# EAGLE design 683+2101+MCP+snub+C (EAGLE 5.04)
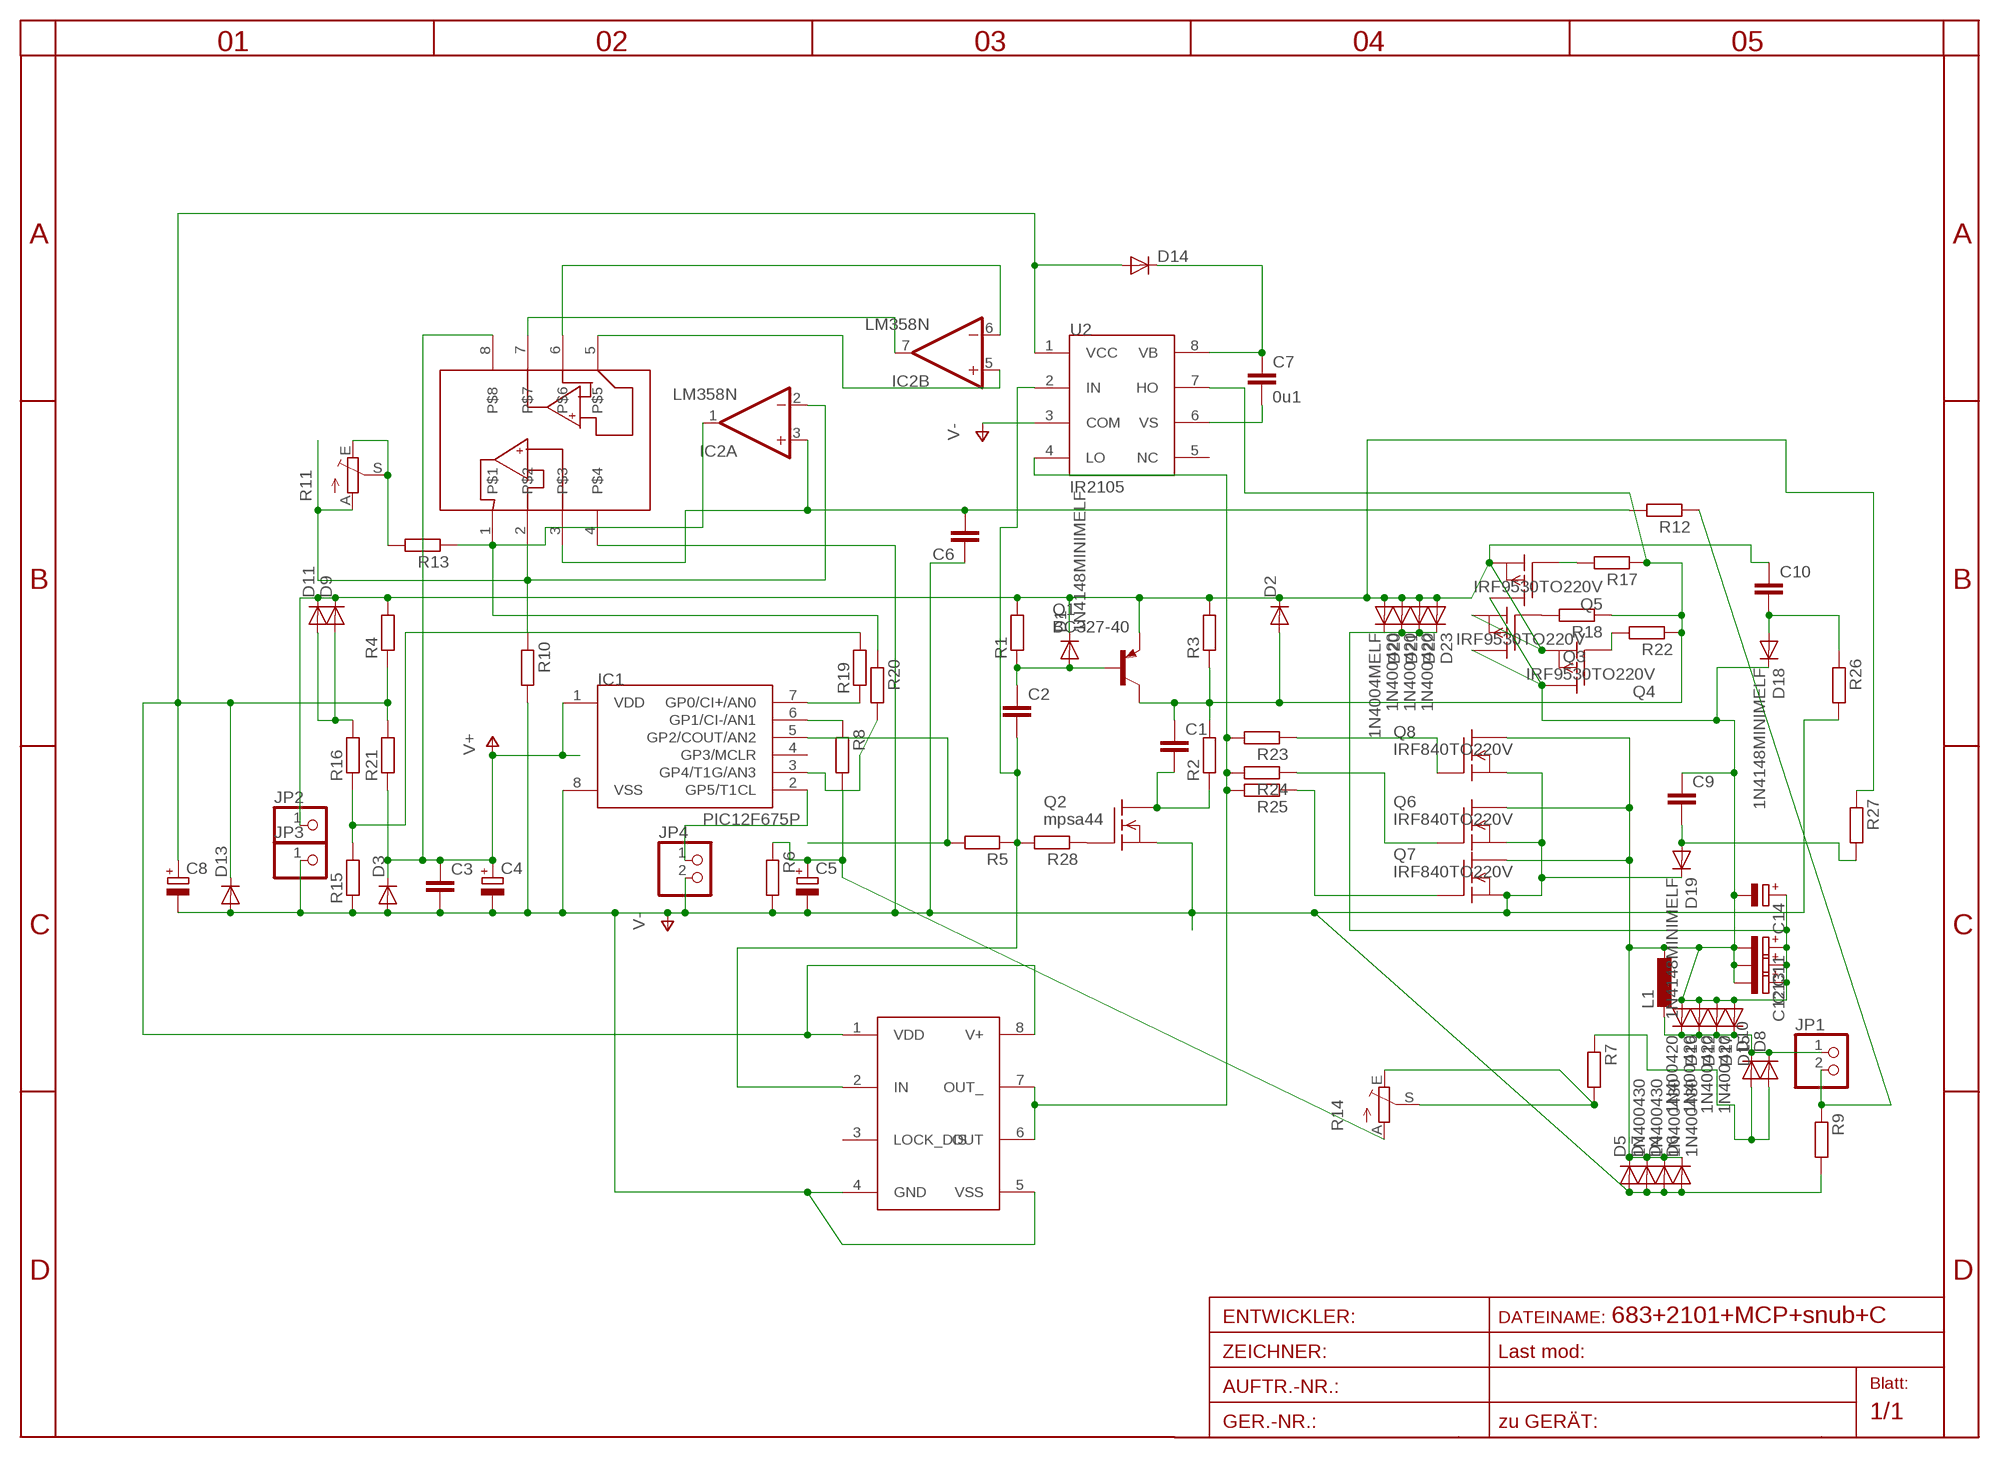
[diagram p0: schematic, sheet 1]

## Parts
C1  C-EU225-074X268  [C225-074X268]
C2  C-EU225-062X268  [C225-062X268]
C3  C-EU050-025X075  [C050-025X075]
C4  CPOL-EU5-13  [2,5-5-FLAT]
C5  CPOL-EU5-13  [2,5-5-FLAT]
C6  C-EU025_050-025X075  [C025_050-025X075]
C7  0u1  C-EU050-030X075  [C050-030X075]
C8  CPOL-EU5-13  [2,5-5-FLAT]
C9  C-EUC1812  [C1812]
C10  C-EUC1812K  [C1812K]
C11  CPOL-EUD  [PANASONIC_D]
C12  CPOL-EUE  [PANASONIC_E]
C13  CPOL-EUE  [PANASONIC_E]
C14  CPOL-EUE  [PANASONIC_E]
D1  1N4148MINIMELF  [MINIMELF]
D2  DIODE-D-5  [D-5]
D3  DIODE-D-2.5  [D-2.5]
D4  1N400430  [DO41-30]
D5  1N400430  [DO41-30]
D6  1N400430  [DO41-30]
D7  1N400430  [DO41-30]
D8  DIODE-D-2.5  [D-2.5]
D9  DIODE-D-2.5  [D-2.5]
D10  DIODE-DO41-30  [DO41-30]
D11  DIODE-D-10  [D-10]
D12  1N400420  [DO41-20]
D13  DIODE-D-2.5  [D-2.5]
D14  DIODE-D-5  [D-5]
D15  1N400420  [DO41-20]
D16  1N400420  [DO41-20]
D17  1N400420  [DO41-20]
D18  1N4148MINIMELF  [MINIMELF]
D19  1N4148MINIMELF  [MINIMELF]
D20  1N4004MELF  [MELF-MLL41]
D21  1N400420  [DO41-20]
D22  1N400420  [DO41-20]
D23  1N400420  [DO41-20]
IC1  PIC12F675P  [DIL8]
IC2  LM358N  [DIL08]
IC3  TC4432X  [SO-08]
JP1  PINHD-1X2  [1X02]
JP2  PINHD-1X1  [1X01]
JP3  PINHD-1X1  [1X01]
JP4  PINHD-1X2  [1X02]
L1  L-EU0204/7  [0204/7]
Q1  BC327-40  [TO92-EBC]
Q2  mpsa44  TN0604N3  [TO-92]
Q3  IRF9530TO220V  [TO220V]
Q4  IRF9530TO220V  [TO220V]
Q5  IRF9530TO220V  [TO220V]
Q6  IRF840TO220V  [TO220V]
Q7  IRF840TO220V  [TO220V]
Q8  IRF840TO220V  [TO220V]
R1  R-EU_0204/2V  [0204V]
R2  R-EU_0207/25  [0207/25]
R3  R-EU_0204/2V  [0204V]
R4  R-EU_0207/10  [0207/10]
R5  R-EU_0207/40  [0207/40]
R6  R-EU_0204/5  [0204/5]
R7  R-EU_0207/15  [0207/15]
R8  R-EU_0207/10  [0207/10]
R9  R-EU_0309/10  [0309/10]
R10  R-EU_0207/15  [0207/15]
R11  TRIM_EU-CIP20C-4MM  [CIP20C-4MM]
R12  R-EU_0207/30  [0207/30]
R13  R-EU_0207/40  [0207/40]
R14  TRIM_EU-CIP20C-4MM  [CIP20C-4MM]
R15  R-EU_0204/5  [0204/5]
R16  R-EU_0207/25  [0207/25]
R17  R-EU_R1206  [R1206]
R18  R-EU_R1206  [R1206]
R19  R-EU_0204/5  [0204/5]
R20  R-EU_0204/5  [0204/5]
R21  R-EU_0207/10  [0207/10]
R22  R-EU_R1206  [R1206]
R23  R-EU_R1206  [R1206]
R24  R-EU_R1206  [R1206]
R25  R-EU_R1206  [R1206]
R26  R-EU_0207/25  [0207/25]
R27  R-EU_0207/30  [0207/30]
R28  R-EU_R0805  [R0805]
U2  IR2105  [DIL08]
U$1  MCP6042SOIC  [SO-08]

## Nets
BB: C2.2 IC3.2(IN) R5.1 R28.2 U2.2(IN)
DRAIN: C9.1 C11.+ C11.- C12.+ C12.- C13.+ C13.- C14.+ C14.- D4.C D5.C D6.C D7.C D12.A D15.A D16.A D17.A D18.C D20.C D21.C D22.C D23.C L1.1 Q3.2(D) Q4.2(D) Q5.2(D) Q6.2(D) Q7.2(D) Q8.2(D)
GATE: C1.1 D2.A Q1.C R2.2 R3.1 R17.1 R18.1 R22.1 U2.7(HO)
MPOINT: C5.+ R6.1 R8.2 R14.A
N$1: C1.2 Q2.3(D) R2.1
N$2: IC2.6(B:-IN) U$1.6
N$3: IC1.5(GP2/COUT/AN2) R5.2
N$4: Q3.1(G) R18.2
N$5: IC1.6(GP1/CI-/AN1) R8.1
N$6: IC2.2(A:-IN) R10.1 R11.A U$1.2
N$7: IC2.1(A:OUT) R13.1 R20.1 U$1.1
N$8: Q2.2(G) R28.1
N$9: C6.2 IC2.3(A:+IN) R12.2 U$1.3
N$10: R7.2 R14.E R14.S
N$11: Q5.1(G) R17.2
N$12: R15.2 R16.1 R19.2
N$13: D9.A D11.A R16.2
N$14: IC1.7(GP0/CI+/AN0) R19.1
N$15: IC1.2(GP5/T1CL) JP4.1
N$16: D8.A D10.A R7.1
N$17: IC1.3(GP4/T1G/AN3) R20.2
N$18: IC2.5(B:+IN) U$1.5
N$20: IC2.7(B:OUT) U$1.7
N$21: C7.2 U2.6(VS)
N$23: Q4.1(G) R22.2
N$24: C10.2 D18.A R26.1
N$25: Q7.1(G) R25.1
N$26: Q6.1(G) R24.1
N$27: Q8.1(G) R23.1
N$28: C9.2 D19.A R27.2
N$29: R11.E R11.S R13.2
N$33: IC3.6(OUT) IC3.7(OUT_) R23.2 R24.2 R25.2 U2.4(LO)
OUT+: D8.C D10.C D12.C D15.C D16.C D17.C JP1.1 L1.2
OUT-: JP1.2 R9.1 R12.1
TB: C2.1 D1.A Q1.B R1.1
V+: C3.1 C4.+ D3.C IC1.1(VDD) R21.1 U$1.8
V-: C3.2 C4.- C5.- C6.1 C8.- D3.A D4.A D5.A D6.A D7.A D13.A D19.C IC1.8(VSS) IC3.4(GND) IC3.5(VSS) JP3.1 JP4.2 Q2.1(S) Q6.3(S) Q7.3(S) Q8.3(S) R6.2 R9.2 R10.2 R15.1 R26.2 U2.3(COM) U$1.4
VB: C7.1 D14.C U2.8(VB)
VCC: C8.+ D13.C D14.A IC3.1(VDD) IC3.8(V+) R4.1 R21.2 U2.1(VCC)
VIN: C10.1 D1.C D2.C D9.C D11.C D20.A D21.A D22.A D23.A JP2.1 Q1.E Q3.3(S) Q4.3(S) Q5.3(S) R1.2 R3.2 R4.2 R27.1
Unconnected: IC1.4(GP3/MCLR) IC3.3(LOCK_DIS) U2.5(NC)

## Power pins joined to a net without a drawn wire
V+: IC2.8(P:V+)
V-: IC2.4(P:V-)

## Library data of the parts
C1-C3 C6 C7 C9 C10 = rcl-2:C-EU: CAPACITOR, European symbol
C4 C5 C8 C11-C14 = rcl-2:CPOL-EU: POLARIZED CAPACITOR, European symbol
D1 D18 D19 = diode-1:1N4148: DIODE
D2 D3 D8-D11 D13 D14 = diode-1:DIODE-: DIODE
D4-D7 D12 D15-D17 D20-D23 = diode-1:1N4004: DIODE
IC1 = microchip-5:PIC12F6*: uPC nW 1k Program Flash memory 2x Timer Comparator 10b A/D converter/ 4xIN
IC2 = linear:LM358: OP AMP also LM158; LM258; LM2904 Source: http://cache.national.com/ds/LM/LM158.pdf
IC3 = microchip:TC4432
JP1 JP4 = pinhead:PINHD-1X2: PIN HEADER
JP2 JP3 = pinhead:PINHD-1X1: PIN HEADER
L1 = rcl-2:L-EU: INDUCTOR, European symbol
Q1 = transistor-pnp:BC327*: PNP Transistror
Q2 = transistor-fet:TN0604N3: N-Channel Enhancement MOSFET 40V; 4A; 0,75Ohm
Q3-Q5 = transistor-fet:IRF9530: P-Channel Enhancement MOSFET (HEXFET); -100V; -12A; 0,3Ohm
Q6-Q8 = transistor-fet:IRF840: N-Channel Enhancement MOSFET (HEXFET); 500V; 8A; 0,85Ohm
R1-R10 R12 R13 R15-R28 = rcl-2:R-EU_: RESISTOR, European symbol
R11 R14 = pot:TRIM_EU-: POTENTIOMETER
U2 = irf-2:IR2105: Half bridge driver
U$1 = microchip-3:MCP6042

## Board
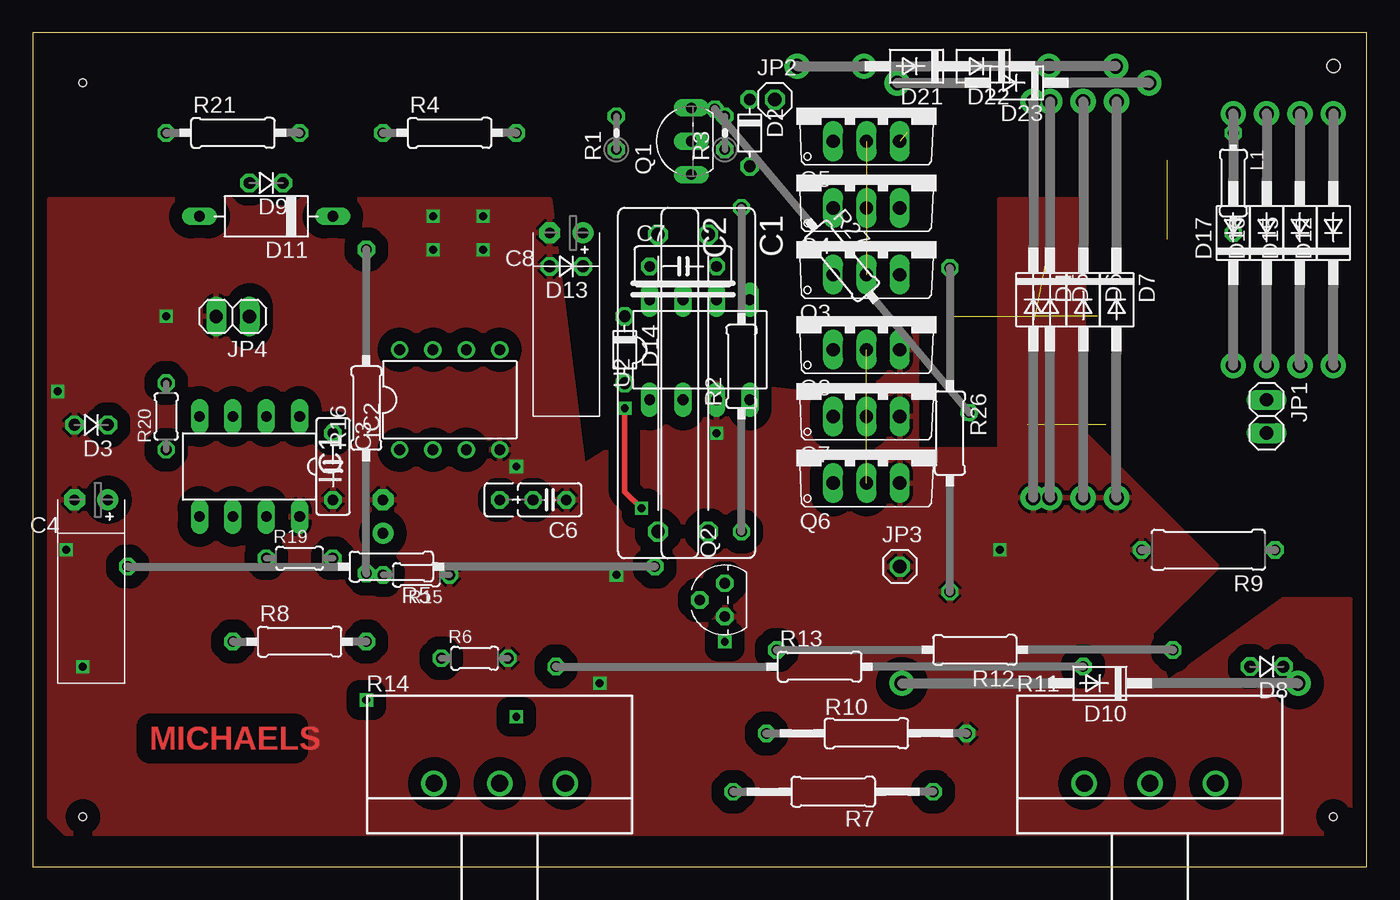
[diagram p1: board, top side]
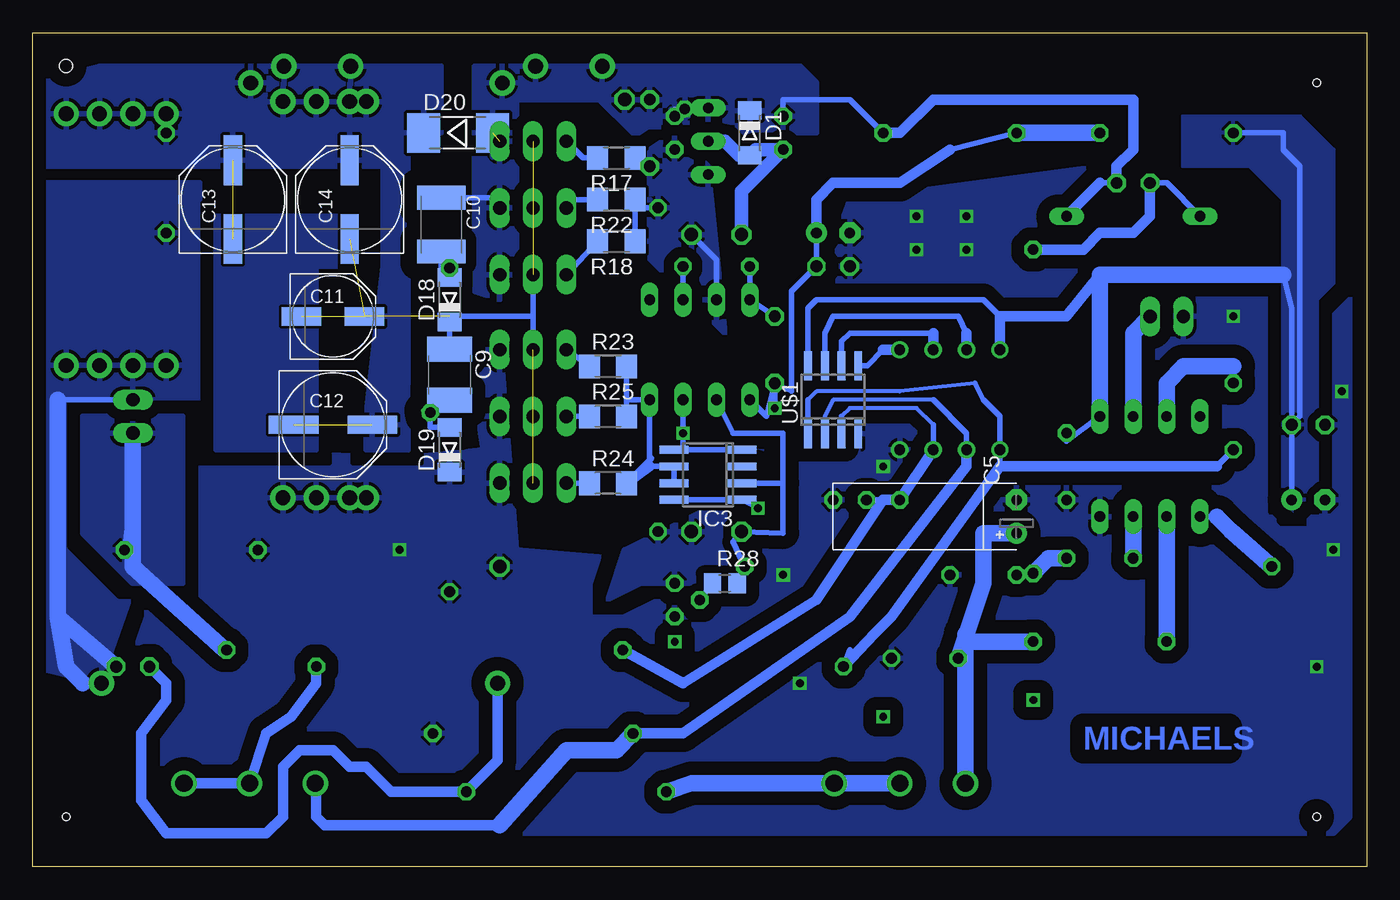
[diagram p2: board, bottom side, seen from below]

Size 101.6 x 63.5 mm. Coordinates in mm from the lower left corner, seen from the top.
Outline: 0,0 101.6,0 101.6,63.5 0,63.5 0,0
Copper layers (1*16): Top 0.035mm / dielectric 1.5mm / Bottom 0.035mm
Design rules "default": minimum track width 10mil, minimum drill 24mil, track to track 8mil, track to pad 8mil, pad to pad 8mil, via to via 8mil, smd to smd 8mil, copper to edge 40mil, drill to drill 8mil, minimum pad ring 10mil, minimum via ring 8mil, stop-mask expansion 4mil, vias tented up to drill 0mil, thermal gap 10mil
Holes 0.6 mm at 3.81,59.69 3.81,3.81 99.06,3.81
Holes 1 mm at 99.06,60.96

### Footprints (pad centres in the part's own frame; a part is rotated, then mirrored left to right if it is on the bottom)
C225-074X268 = drill 1.016 octagon: 1 -11.303,0; 2 11.303,0
C225-062X268 = drill 1.016 octagon: 1 -11.303,0; 2 11.303,0
C050-025X075 = drill 0.813 octagon: 1 -2.54,0; 2 2.54,0
2,5-5-FLAT = drill 0.813 pad 1.6 round: + -1.27,0 | drill 0.813 pad 1.6 octagon: - 1.27,0
C025_050-025X075 = drill 0.813 octagon: 1 -1.27,0; 2 1.27,0; 3 3.81,0
C050-030X075 = drill 0.813 octagon: 1 -2.54,0; 2 2.54,0
C1812 = smd 1.9 x 3.4: 1 -1.95,0; 2 1.95,0
C1812K = smd 1.8 x 3.7: 1 -2.05,0; 2 2.05,0
PANASONIC_D = smd 3 x 1.4: + 2.4,0; - -2.4,0
PANASONIC_E = smd 3.8 x 1.4: + 3,0; - -3,0
MINIMELF = smd 1.4 x 1.8: A 1.7,0; C -1.7,0
D-5 = drill 0.9 octagon: A 2.54,0; C -2.54,0
D-2.5 = drill 0.9 octagon: A 1.27,0; C -1.27,0
DO41-30 = drill 1.118 pad 1.93 round: A 15.08,0; C -15.08,0
D-10 = drill 0.813 long: A 5.08,0; C -5.08,0
DO41-20 = drill 1.118 pad 1.93 round: A 9.08,0; C -10.08,0
MELF-MLL41 = smd 2.5 x 3: A 2.625,0; C -2.625,0
DIL8 = drill 0.813 long: 1 -3.81,-3.81; 2 -1.27,-3.81; 3 1.27,-3.81; 4 3.81,-3.81; 5 3.81,3.81; 6 1.27,3.81; 7 -1.27,3.81; 8 -3.81,3.81
DIL08 = drill 0.813 pad 1.27 round: 1 -3.81,-3.81; 2 -1.27,-3.81; 3 1.27,-3.81; 4 3.81,-3.81; 5 3.81,3.81; 6 1.27,3.81; 7 -1.27,3.81; 8 -3.81,3.81
SO-08 = smd 0.6 x 2.2: 1 -1.905,-2.6; 2 -0.635,-2.6; 3 0.635,-2.6; 4 1.905,-2.6; 5 1.905,2.6; 6 0.635,2.6; 7 -0.635,2.6; 8 -1.905,2.6
1X02 = drill 1.016 long: 1 -1.27,0; 2 1.27,0
1X01 = drill 1.016 octagon: 1 0,0
0204/7 = drill 0.813 octagon: 1 -3.81,0; 2 3.81,0
TO92-EBC = drill 0.813 long: B 0,-1.27; C -2.54,-1.27; E 2.54,-1.27
TO-92 = drill 0.813 octagon: 1 -1.27,0; 2 0,1.905; 3 1.27,0
TO220V = drill 1.016 long: 1 -2.54,-2.54; 2 0,-2.54; 3 2.54,-2.54
0204V = drill 0.813 octagon: 1 -1.27,0; 2 1.27,0
0207/25 = drill 0.813 octagon: 1 -12.58,0; 2 12.08,0
0207/10 = drill 0.813 octagon: 1 -5.08,0; 2 5.08,0
0207/40 = drill 0.813 octagon: 1 -20.08,0; 2 20.08,0
0204/5 = drill 0.813 octagon: 1 -2.54,0; 2 2.54,0
0207/15 = drill 0.813 octagon: 1 -7.62,0; 2 7.62,0
0309/10 = drill 0.813 octagon: 1 -5.08,0; 2 5.08,0
CIP20C-4MM = drill 1.3 pad 1.93 round: A -5,0; E 5,0; S 0,0
0207/30 = drill 0.813 octagon: 1 -15.08,0; 2 15.08,0
R1206 = smd 1.6 x 1.803: 1 -1.422,0; 2 1.422,0
R0805 = smd 1.3 x 1.5: 1 -0.95,0; 2 0.95,0
DIL08' = drill 0.813 long: 1 -3.81,-3.81; 2 -1.27,-3.81; 3 1.27,-3.81; 4 3.81,-3.81; 5 3.81,3.81; 6 1.27,3.81; 7 -1.27,3.81; 8 -3.81,3.81

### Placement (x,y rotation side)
C1  51.44,36.83 270 top
C2  47.62,36.83 270 top
C3  22.86,30.48 270 top
C4  4.45,27.94 180 top
C5  26.67,26.67 90 bottom
C6  39.37,27.94 180 top
C7  49.53,45.72 0 top
C8  40.64,48.26 180 top
C9  69.85,37.47 270 bottom
C10  70.48,48.9 270 bottom
C11  78.74,41.91 0 bottom
C12  78.74,33.66 0 bottom
C13  86.36,50.8 90 bottom
C14  77.47,50.8 90 bottom
D1  46.99,55.88 270 bottom
D2  54.61,55.88 270 top
D3  4.45,33.66 180 top
D4  76.2,43.18 270 top
D5  77.47,43.18 270 top
D6  80.01,43.18 270 top
D7  82.55,43.18 270 top
D8  93.98,15.24 180 top
D9  17.78,52.07 180 top
D10  81.28,13.97 180 top
D11  17.78,49.53 180 top
D12  99.06,48.26 90 top
D13  40.64,45.72 180 top
D14  45.09,39.37 270 top
D15  96.52,48.26 90 top
D16  93.98,48.26 90 top
D17  91.44,48.26 90 top
D18  69.85,43.18 90 bottom
D19  69.85,31.75 90 bottom
D20  69.22,55.88 0 bottom
D21  67.31,60.96 180 top
D22  72.39,60.96 180 top
D23  74.93,59.69 180 top
IC1  16.51,30.48 180 top
IC2  31.75,35.56 0 top
IC3  50.16,29.84 90 bottom
JP1  93.98,34.29 270 top
JP2  56.52,58.42 0 top
JP3  66.04,22.86 0 top
JP4  15.24,41.91 180 top
L1  91.44,52.07 270 top
Q1  48.9,55.24 90 top
Q2  52.7,20.32 90 top
Q3  63.5,47.62 0 top
Q4  63.5,52.7 0 top
Q5  63.5,57.78 0 top
Q6  63.5,31.75 0 top
Q7  63.5,36.83 0 top
Q8  63.5,41.91 0 top
R1  44.45,55.88 90 top
R2  53.98,38.1 90 top
R3  52.7,55.88 90 top
R4  31.75,55.88 0 top
R5  27.3,22.86 180 top
R6  33.66,15.88 0 top
R7  60.96,5.71 180 top
R8  20.32,17.14 0 top
R9  89.53,24.13 180 top
R10  63.5,10.16 0 top
R11  85.09,6.35 0 top
R12  71.75,16.51 180 top
R13  59.93,15.24 0 top
R14  35.56,6.35 0 top
R15  29.21,22.23 180 top
R16  25.4,34.92 90 top
R17  57.15,53.98 180 bottom
R18  57.15,47.62 180 bottom
R19  20.32,23.5 0 top
R20  10.16,34.29 90 top
R21  15.24,55.88 0 top
R22  57.15,50.8 180 bottom
R23  57.78,38.1 0 bottom
R24  57.78,29.21 0 bottom
R25  57.78,34.29 0 bottom
R26  69.85,33.02 270 top
R27  61.63,46.14 310 top
R28  48.9,21.59 0 bottom
U2  IR2105  [DIL08']  50.8,39.37 0 top
U$1  40.64,35.56 0 bottom

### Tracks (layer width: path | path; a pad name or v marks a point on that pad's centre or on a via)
BB
  Bottom 0.406: 44.45,29.21 44.45,25.4 C2.2 48.26,24.77 R5.1 R28.2 | 44.45,29.21 IC3.2 | 44.45,29.21 44.45,33.02 48.26,33.02 U2.2
DRAIN  (9 unrouted)
  Bottom 0.406: C9.1 D18.C 69.85,41.91 63.5,41.91 | Q8.2 63.5,41.91 | 63.5,41.91 Q3.2
  pour Bottom (isolate 1.016, rank 5): 101.6,53.34 74.93,53.34 70.48,55.88 70.48,60.96 96.52,60.96 101.6,59.69
  pour Bottom (isolate 1.27): 76.2,34.29 76.2,31.75 73.03,31.75 73.03,55.88 77.47,55.88 74.93,53.34 74.93,45.72
GATE
  Bottom 0.406: C1.1 49.53,46.23 U2.7 | R18.1 R22.1 55.11,50.18 R2.2 | D2.A 55.09,53.34 R17.1
  pour Bottom (isolate 0.813, rank 2): 50.16,53.34 52.7,55.88 54.61,54.61 54.61,46.35 48.9,40.64
MPOINT
  Bottom 0.406: 29.84,17.14 R6.1 30.56,17.7
  Bottom 1.27: 29.84,17.14 R8.2 | R14.A 30.56,17.7 | R6.1 29.21,21.59 29.21,25.4 C5.+
N$1
  pour Bottom (isolate 0.61, rank 3): 48.9,27.94 56.52,24.13 57.78,20.32 55.24,21.59 48.9,21.59
N$2
  Bottom 0.406: U$1.6 40.01,40.01 39.37,40.64 33.02,40.64
  Bottom 0.813: IC2.6 33.02,40.64
N$3
  Bottom 0.406: 11.43,26.67 IC1.5
  Bottom 1.27: R5.2 10.4,25.64 11.43,26.67
N$4
  Bottom 0.406: R18.2 Q3.1
N$5
  Bottom 1.27: R8.1 IC1.6
N$6
  Bottom 0.305: U$1.2 41.27,34.29 40.64,35.56 33.02,35.56
  Bottom 0.406: 33.02,35.56 30.48,33.02 IC2.2
  Bottom 0.813: R10.1 52.07,10.16 39.37,19.05 30.48,30.48 IC2.2 | 66.04,3.17 79.38,3.17 80.01,3.81 80.01,6.27 R11.A
  Bottom 1.27: 66.04,3.17 60.96,8.89 57.15,8.89 R10.1
N$7
  Bottom 0.305: 29.84,36.83 35.56,36.2 41.91,36.2 42.55,35.56
  Bottom 0.406: 29.84,36.83 29.21,35.56 27.94,34.29 IC2.1 27.94,30.48 | 42.55,35.56 U$1.1 | R13.1 39.37,16.51 | R20.1 11.43,30.48
  Bottom 0.813: 11.43,30.48 27.94,30.48 36.2,19.05 37.47,17.78 R13.1
N$8
  Bottom 0.406: R28.1 Q2.2
N$9
  Bottom 0.305: 33.02,33.66 34.29,34.92 39.37,34.92 40.01,34.29
  Bottom 0.406: IC2.3 33.02,33.66 | 40.01,34.29 U$1.3 | 36.83,27.94 C6.2
  Bottom 0.813: IC2.3 35.56,27.94 36.83,27.94 41.91,20.32 52.07,13.97 R12.2
N$10
  Bottom 1.27: R14.S R14.E 51.44,6.35 R7.2
N$11
  Bottom 0.406: R17.2 59.69,53.98 Q5.1
N$12
  Bottom 0.406: R15.2 25.52,22.23 R16.1
  Bottom 1.27: R19.2 24.25,23.5 R16.1
N$13
  Bottom 0.406: D9.A 15.24,52.07 D11.A | 25.39,46.99 R16.2
  Bottom 0.813: D9.A 16.51,49.53 17.78,48.26 20.32,48.26 21.59,46.99 25.39,46.99
N$14
  Bottom 1.27: R19.1 IC1.7
N$15
  Bottom 1.27: IC1.2 17.78,40.64 JP4.1
N$16
  Bottom 0.813: D8.A 91.44,13.97 91.44,12.7 93.34,10.16 93.34,5.08 91.44,2.54 83.82,2.54 82.55,3.81 82.55,7.62 81.28,8.89 78.74,8.89 77.47,7.62 76.2,7.62 74.3,5.71 R7.1 66.2,8.1 D10.A
N$17
  Bottom 0.406: R20.2 10.16,38.1
  Bottom 1.27: 10.16,38.1 13.97,38.1 15.24,36.83 IC1.3
N$18
  Bottom 0.406: U$1.5 38.04,38.16 36.83,39.37
  Bottom 0.813: IC2.5 36.83,39.37
N$20
  Bottom 0.406: U$1.7 41.27,40.64 40.64,41.91 31.11,41.91 30.48,40.64
  Bottom 0.813: IC2.7 30.48,40.64
N$21
  Bottom 0.406: U2.6 C7.2
N$22  (via drill 0.6)
  other vias: 36.83,11.43
N$23
  Bottom 0.406: R22.2 60.33,50.8 Q4.1
N$24
  Bottom 0.406: D18.A R26.1 70.48,45.6 C10.2
N$25
  Bottom 0.406: R25.1 Q7.1
N$26
  Bottom 0.406: R24.1 Q6.1
N$27
  Bottom 0.406: R23.1 Q8.1
N$28
  Bottom 0.406: C9.2 71.33,35.52 R27.2 71.33,33.45 D19.A
N$29
  Bottom 0.813: R13.2 80.01,13.97 81.92,11.43 83.82,10.16 R11.S R11.E
N$30  (via drill 0.6)
  other vias: 25.4,12.7
N$31
  pour Bottom: 77.47,49.53 87.63,49.53 87.63,31.75 80.01,31.75 80.01,45.72 77.47,45.72
N$33
  Bottom 0.406: 54.61,30.96 U2.4 56.36,35.56 | R24.2 54.61,30.96 | 56.36,35.56 R25.2 | 56.36,35.56 R23.2 | IC3.7 IC3.6 54.61,30.48 | 54.61,30.96 54.46,31.11
  Bottom 0.813: 54.61,30.48 R24.2
N$35  (via drill 0.6)
  other vias: 52.7,17.14
OUT+
  Bottom 0.406: 99.69,35.56 JP1.1 | D10.C 97.79,13.97
  Bottom 1.27: 99.69,19.05 99.69,35.56 | 99.69,19.05 D8.C | 99.69,19.05 99.06,15.24 97.79,13.97
  pour Bottom (isolate 1.016, rank 5): 88.9,52.07 101.6,52.07 101.6,15.24 96.52,13.97 88.9,35.56
OUT-
  Bottom 0.406: R12.1 87,16.51 | 93.98,29.21 R9.1
  Bottom 1.27: 87,16.51 93.98,22.86 93.98,29.21 JP1.2
  pour Bottom (isolate 0.813): 90.17,34.29 97.79,34.29 97.79,33.02 97.79,25.4 93.98,21.59 90.17,21.59 90.17,31.75
TB
  Bottom 1.016: C2.1 47.62,51.44 R1.1 46.56,54.61 D1.A 47.83,54.18 48.9,55.24 Q1.B
V+
  Bottom 0.406: R21.1 6.35,55.88 6.35,54.61 5.08,53.34 5.08,34.29 D3.C | D3.C 5.71,42.55 6.35,45.09 | IC1.1 22.86,32.38 C3.1 | U$1.8 42.55,42.55 41.91,43.18 29.21,43.18 27.94,41.91 | C4.+ D3.C
  Bottom 0.813: 20.32,45.09 22.86,41.91 27.94,41.91 IC2.8
  Bottom 1.27: 6.35,45.09 20.32,45.09 IC1.1
  pour Bottom (isolate 0.61, rank 3): 13.97,57.15 5.08,57.15 2.54,54.61 2.54,44.45 3.81,43.18 3.81,27.94 5.08,26.67 6.35,27.94 6.35,50.8 8.89,53.34 13.97,53.34
V-  (via drill 0.6)
  Bottom 0.406: IC3.4 52.07,31.75 | 52.07,31.75 IC3.5 | 52.07,31.75 v52.07,33.02 U2.3
  other vias: 36.83,30.48 44.45,22.23 43.18,13.97 73.66,24.13 10.16,41.91 30.48,49.53 34.29,49.53 34.29,46.99 30.48,46.99 1.91,36.2 2.54,24.13 3.81,15.24
  pour Top (isolate 1.016, rank 5): 1.27,50.8 39.37,50.8 41.91,30.48 52.07,36.83 63.5,35.56 64.77,40.64 67.31,40.64 67.31,31.75 73.66,31.75 73.66,50.8 80.01,50.8 80.01,33.02 90.17,22.86 85.09,17.78 86.36,13.97 95.25,20.32 100.33,20.32 100.33,3.81 99.06,2.54 2.54,2.54 1.27,3.81
  pour Bottom (isolate 1.016, rank 6): 1.27,55.88 39.37,50.8 49.53,22.86 64.77,24.13 66.04,40.64 68.58,40.64 67.31,31.75 73.66,31.11 86.36,31.75 88.9,31.75 92.71,27.94 93.98,25.4 93.98,22.86 97.79,22.86 100.33,20.32 100.33,3.81 99.06,2.54 2.54,2.54 1.27,3.81
VB
  Bottom 0.406: C7.1 U2.8 D14.C
VCC  (via drill 0.6)
  Top 0.406: v46.35,27.3 45.09,28.57 v45.09,34.92
  Bottom 0.406: D14.A 43.81,36.2 43.81,43.81 D13.C C8.+ | 31.75,54.61 R4.1 | D14.A 45.72,34.29 U2.1 | IC3.8 IC3.1 v46.35,27.3 | v45.09,34.92 D14.A
  Bottom 0.813: 31.75,54.61 35.56,52.07 40.64,52.07 41.91,50.8 C8.+
  Bottom 1.27: R4.1 R21.2
VIN  (1 unrouted)
  Bottom 0.406: D9.C 20.32,52.07 | R4.2 39.37,58.42 44.45,58.42 R1.2 | C10.1 66.04,50.95 Q4.3 | R27.1 52.7,57.69 R3.2
  Bottom 0.813: 20.32,52.07 D11.C | R4.2 35.56,55.88 33.02,58.42 17.78,58.42 17.78,54.61 19.05,53.34 D9.C
  pour Bottom (isolate 0.813, rank 3): 67.94,43.81 67.94,60.96 43.18,60.96 41.91,59.69 41.91,55.88 55.88,55.88 58.42,58.42 64.77,58.42 64.77,44.45 66.04,43.18

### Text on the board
Top: MICHAELS
Bottom: MICHAELS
